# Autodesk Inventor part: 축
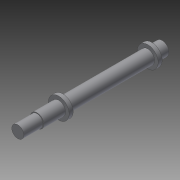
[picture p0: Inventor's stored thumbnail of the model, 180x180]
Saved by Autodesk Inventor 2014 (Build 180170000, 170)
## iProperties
Created: 2014-12
Part Number: 축
Material: 일반
Document SubType Name: Modeling
Designer: Owner
Density: 1 g/cm^3
Appearance: 기본값
Author: Owner
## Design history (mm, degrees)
sketch "스케치2"
  geometry: L1 (-90, 0)-(90, 0); L2 (-90, 0)-(-90, 7.5); L3 (-90, 7.5)-(-66, 7.5); L4 (-66, 7.5)-(-66, 8.5); L5 (-66, 8.5)-(-39, 8.5); L6 (-39, 8.5)-(-39, 13); L7 (-39, 13)-(-34, 13); L8 (-34, 13)-(-34, 8.5); L9 (-34, 8.5)-(72, 8.5); L10 (72, 8.5)-(72, 13); L11 (72, 13)-(77, 13); L12 (77, 13)-(77, 8.5); L13 (77, 8.5)-(90, 8.5); L14 (90, 8.5)-(90, 0); 3 further points
  constraints: 28 end point, 6 parallel, 6 perpendicular, 2 midpoint, 1 coincident, 1 collinear, 1 horizontal, 1 horizontal alignment
  dimensions: "d0" = 180 distance of L1.start L1.end; "d1" = 15 diameter of L3 L1; "d2" = 17 diameter of L5 L1; "d3" = 24 distance of L2.end L3.end; "d4" = 27 distance of L4.end L5.end; "d5" = 26 diameter of L7 L1; "d6" = 5 distance of L6.end L7.end; "d7" = 17 diameter of L13 L1; "d8" = 26 diameter of L11 L1; "d9" = 5 distance of L10.end L11.end; "d10" = 13 distance of L12.end L13.end
revolve "회전1" sketch "스케치2" stored, may be unused: angle "d11" = 90 deg
node "솔리드1"
